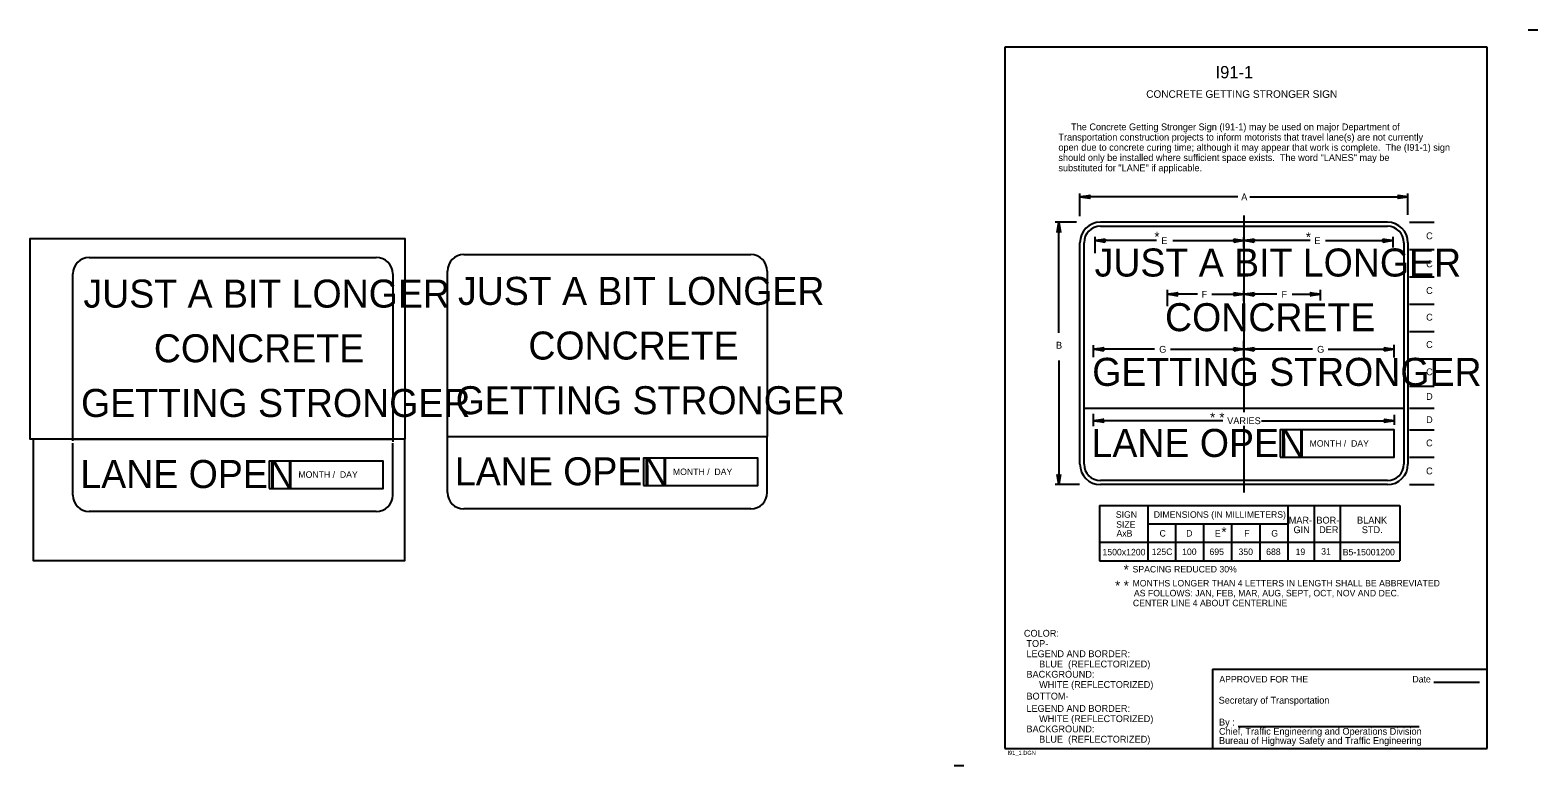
# Model space of a CAD drawing. Extents: x -0.356 to 0.195, y -0.006 to 0.263.
import ezdxf

# ---------------------------------------------------------------- set-up
doc = ezdxf.new("R2010")
doc.units = 0
doc.layers.add('1', color=7, linetype='Continuous')
doc.layers.add('3', color=7, linetype='Continuous')

# ---------------------------------------------------------------- blocks, each defined once
blk = doc.blocks.new('RARROW')
at = {"layer": '3'}
for p, q in [((-2.156, 0.285), (-2.2665, 0.384625)), ((-2.2665, 0.384625), (0, 0)), ((0, 0), (-2.2665, -0.379125)), ((-2.156, 0.285), (-2.075625, 0.12075)), ((0, 0), (-2.156, 0.285)), ((-2.14975, -0.2705), (0, 0)), ((-2.075625, 0.12075), (0, 0)), ((0, 0), (-2.074, -0.108)), ((-2.2665, -0.379125), (-2.14975, -0.2705)), ((-2.074, -0.108), (-2.14975, -0.2705))]:
    blk.add_line(p, q, dxfattribs=at)

msp = doc.modelspace()

# ---------------------------------------------------------------- linework, layer by layer
at = {"layer": '1'}
for p, q in [((0.195, 0.26275), (0.1915, 0.26275)), ((0.1765, 0.2565), (0, 0.2565)), ((0, 0.2565), (0, 0)), ((0.1765, 0), (0.1765, 0.2565)), ((0.076, 0.029), (0.1765, 0.029)), ((0.076, 0.029), (0.076, 0)), ((0.157, 0.02425), (0.173625, 0.02425)), ((0.085375, 0.008), (0.151625, 0.008)), ((0, 0), (0.1765, 0)), ((-0.015, -0.006375), (-0.0185, -0.006375))]:
    msp.add_line(p, q, dxfattribs=at)
at = {"layer": '3'}
for p, q in [((0.0275, 0.19475), (0.0275, 0.203)), ((0.08525, 0.20175), (0.0275, 0.20175)), ((0.089625, 0.20175), (0.1475, 0.20175)), ((0.1475, 0.19525), (0.1475, 0.203)), ((0.0875, 0.195), (0.0875, 0.123)), ((0.02625, 0.1925), (0.0185, 0.1925)), ((0.01975, 0.152), (0.01975, 0.1925)), ((0.14, 0.1925), (0.035, 0.1925)), ((0.035, 0.191), (0.14, 0.191)), ((0.148, 0.1925), (0.157125, 0.1925)), ((0.0275, 0.104), (0.0275, 0.185)), ((0.029, 0.104), (0.029, 0.185)), ((0.033, 0.187125), (0.033, 0.181125)), ((0.0555, 0.18575), (0.033, 0.18575)), ((0.0615, 0.18575), (0.0875, 0.18575)), ((0.0875, 0.18325), (0.0875, 0.187)), ((0.11175, 0.18575), (0.0875, 0.18575)), ((0.117375, 0.18575), (0.142, 0.18575)), ((0.142, 0.187125), (0.142, 0.18325)), ((0.146, 0.185), (0.146, 0.104)), ((0.1475, 0.185), (0.1475, 0.104)), ((0.148, 0.1825), (0.157125, 0.1825)), ((-0.334875, 0.179625), (-0.229875, 0.179625)), ((-0.197875, 0.180625), (-0.092875, 0.180625)), ((-0.340875, 0.1125), (-0.340875, 0.173625)), ((-0.223875, 0.173625), (-0.223875, 0.112125)), ((-0.203875, 0.114125), (-0.203875, 0.174625)), ((-0.086875, 0.174625), (-0.086875, 0.114125)), ((0.148, 0.1725), (0.157125, 0.1725)), ((0.0595, 0.16175), (0.0595, 0.16775)), ((0.0705, 0.166125), (0.0595, 0.166125)), ((0.07575, 0.166125), (0.0875, 0.166125)), ((0.0875, 0.163625), (0.0875, 0.167375)), ((0.0995, 0.166125), (0.0875, 0.166125)), ((0.105125, 0.166125), (0.1155, 0.166125)), ((0.1155, 0.163875), (0.1155, 0.16775)), ((0.148, 0.1625), (0.157125, 0.1625)), ((0.0875, 0.145375), (0.0875, 0.149125)), ((0.148, 0.1525), (0.157125, 0.1525)), ((0.0325, 0.143125), (0.0325, 0.1475)), ((0.05475, 0.146), (0.0325, 0.146)), ((0.060625, 0.146), (0.0875, 0.146)), ((0.0875, 0.1435), (0.0875, 0.14725)), ((0.112625, 0.146), (0.0875, 0.146)), ((0.11825, 0.146), (0.1425, 0.146)), ((0.1425, 0.143), (0.1425, 0.147625)), ((0.01975, 0.141875), (0.01975, 0.0965)), ((0.148, 0.1425), (0.157125, 0.1425)), ((0.148, 0.1325), (0.157125, 0.1325)), ((0.029, 0.1245), (0.146, 0.1245)), ((0.0325, 0.117875), (0.0325, 0.122375)), ((0.1425, 0.122), (0.1425, 0.118375)), ((0.148, 0.1245), (0.157125, 0.1245)), ((0.07975, 0.119875), (0.0325, 0.119875)), ((0.0875, 0.118), (0.0875, 0.093625)), ((0.093875, 0.119875), (0.1425, 0.119875)), ((0.148, 0.1165), (0.157125, 0.1165)), ((-0.340875, 0.113125), (-0.223875, 0.113125)), ((-0.340875, 0.092625), (-0.340875, 0.111625)), ((-0.223875, 0.092625), (-0.223875, 0.111625)), ((-0.203875, 0.114125), (-0.086875, 0.114125)), ((-0.203875, 0.093625), (-0.203875, 0.114125)), ((-0.086875, 0.093625), (-0.086875, 0.114125)), ((0.148, 0.1065), (0.157125, 0.1065)), ((0.027375, 0.0965), (0.0185, 0.0965)), ((0.14, 0.098), (0.035, 0.098)), ((0.14, 0.0965), (0.035, 0.0965)), ((0.148, 0.0965), (0.157125, 0.0965)), ((0.034625, 0.088875), (0.1445, 0.088875)), ((0.034625, 0.088875), (0.034625, 0.068625)), ((0.052375, 0.088875), (0.052375, 0.068625)), ((0.1035, 0.088875), (0.1035, 0.068625)), ((0.113125, 0.088875), (0.113125, 0.068625)), ((0.12275, 0.088875), (0.12275, 0.068625)), ((0.1445, 0.088875), (0.1445, 0.068625)), ((-0.229875, 0.086625), (-0.334875, 0.086625)), ((-0.092875, 0.087625), (-0.197875, 0.087625)), ((0.1035, 0.082), (0.052375, 0.082)), ((0.0625, 0.082), (0.0625, 0.068625)), ((0.07275, 0.082), (0.07275, 0.068625)), ((0.083, 0.082), (0.083, 0.068625)), ((0.09325, 0.082), (0.09325, 0.068625)), ((0.034625, 0.0755), (0.1445, 0.0755)), ((0.034625, 0.068625), (0.1445, 0.068625))]:
    msp.add_line(p, q, dxfattribs=at)
for points in [[(-0.2195, 0.113125), (-0.3565, 0.113125), (-0.3565, 0.1865), (-0.2195, 0.1865)], [(0.10075, 0.1065), (0.1425, 0.1065), (0.1425, 0.1165), (0.10075, 0.1165)], [(-0.2195, 0.113125), (-0.355375, 0.113125), (-0.355375, 0.06875), (-0.2195, 0.06875)], [(-0.269125, 0.095125), (-0.227375, 0.095125), (-0.227375, 0.105125), (-0.269125, 0.105125)], [(-0.132125, 0.096125), (-0.090375, 0.096125), (-0.090375, 0.106125), (-0.132125, 0.106125)]]:
    msp.add_lwpolyline(points, close=True, dxfattribs=at)
for centre, radius, start, end in [((0.035, 0.185), 0.0075, 90, 180), ((0.035, 0.185), 0.006, 90, 180), ((0.14, 0.185), 0.0075, 0, 90), ((0.14, 0.185), 0.006, 0, 90), ((-0.334875, 0.173625), 0.006, 90, 180), ((-0.229875, 0.173625), 0.006, 0, 90), ((-0.197875, 0.174625), 0.006, 90, 180), ((-0.092875, 0.174625), 0.006, 0, 90), ((0.035, 0.104), 0.0075, 180, 270), ((0.035, 0.104), 0.006, 180, 270), ((0.14, 0.104), 0.0075, 270, 0), ((0.14, 0.104), 0.006, 270, 0), ((-0.334875, 0.092625), 0.006, 180, 270), ((-0.229875, 0.092625), 0.006, 270, 0), ((-0.197875, 0.093625), 0.006, 180, 270), ((-0.092875, 0.093625), 0.006, 270, 0)]:
    msp.add_arc(centre, radius, start, end, dxfattribs=at)

# ---------------------------------------------------------------- block references
at = {"layer": '3', "xscale": 0.0016545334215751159, "yscale": 0.0016366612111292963}
for p, rotation in [((0.0275, 0.20175), 180), ((0.01975, 0.1925), 90), ((0.033, 0.18575), 180), ((0.0875, 0.18575), 180), ((0.0595, 0.166125), 180), ((0.0875, 0.166125), 180), ((0.0325, 0.146), 180), ((0.0875, 0.146), 180), ((0.0325, 0.119875), 180), ((0.01975, 0.0965), -90)]:
    msp.add_blockref('RARROW', p, dxfattribs=dict(at, rotation=rotation))
for p in [(0.1475, 0.20175), (0.0875, 0.18575), (0.142, 0.18575), (0.0875, 0.166125), (0.1155, 0.166125), (0.0875, 0.146), (0.1425, 0.146), (0.1425, 0.119875)]:
    msp.add_blockref('RARROW', p, dxfattribs=at)

# ---------------------------------------------------------------- texts
at = {"layer": '1'}
for s, height, p in [('I91-1', 0.0045, (0.077125, 0.245125)), ('CONCRETE GETTING STRONGER SIGN', 0.00275025, (0.05175, 0.238)), ('COLOR:', 0.0024998, (0.007, 0.040875)), (' TOP-', 0.0024998, (0.007, 0.037125)), (' LEGEND AND BORDER:', 0.00249975, (0.007, 0.033375)), (' BACKGROUND:', 0.00249975, (0.007, 0.025875)), ('      BLUE  (REFLECTORIZED)', 0.00249975, (0.007, 0.029625)), ('      WHITE (REFLECTORIZED)', 0.00249975, (0.007, 0.022125)), ('APPROVED FOR THE', 0.00237525, (0.0785, 0.024125)), ('Date ', 0.0023752, (0.149125, 0.024125)), (' BOTTOM-', 0.0024998, (0.007, 0.017875)), ('Secretary of Transportation', 0.00249975, (0.07825, 0.016375)), (' LEGEND AND BORDER:', 0.00249975, (0.007, 0.013375)), ('      WHITE (REFLECTORIZED)', 0.00249975, (0.007, 0.009625)), (' BACKGROUND:', 0.00249975, (0.007, 0.005875)), ('Chief, Traffic Engineering and Operations Division', 0.00249975, (0.078375, 0.005)), ('By :', 0.0024998, (0.078375, 0.008375)), ('      BLUE  (REFLECTORIZED)', 0.00249975, (0.007, 0.002125)), ('Bureau of Highway Safety and Traffic Engineering', 0.00249975, (0.078375, 0.001625)), ('I91_1.DGN', 0.0015, (0.001, -0.002375))]:
    msp.add_text(s, height=height, dxfattribs=at).set_placement(p)
at = {"layer": '3'}
for s, height, p in [('     The Concrete Getting Stronger Sign (I91-1) may be used on major Department of', 0.00249975, (0.019625, 0.226125)), ('Transportation construction projects to inform motorists that travel lane(s) are not currently', 0.00249975, (0.019625, 0.222375)), ('open due to concrete curing time; although it may appear that work is complete.  The (I91-1) sign ', 0.00249975, (0.019625, 0.218625)), ('should only be installed where sufficient space exists.  The word "LANES" may be', 0.00249975, (0.019625, 0.214875)), ('substituted for "LANE" if applicable.', 0.00249975, (0.019625, 0.211125)), ('A', 0.0025, (0.0865, 0.2005)), ('*', 0.003599, (0.05475, 0.185375)), ('*', 0.003599, (0.110125, 0.18525)), ('C', 0.0025, (0.154125, 0.18625)), ('JUST A BIT LONGER', 0.01025025, (0.032875, 0.172625)), ('E', 0.0025, (0.05725, 0.1845)), ('E', 0.0025, (0.11325, 0.1845)), ('C', 0.0025, (0.154125, 0.176)), ('JUST A BIT LONGER', 0.01025025, (-0.337, 0.16125)), ('JUST A BIT LONGER', 0.01025025, (-0.2, 0.16225)), ('F', 0.0025, (0.072, 0.164875)), ('F', 0.0025, (0.10125, 0.164875)), ('C', 0.0025, (0.154125, 0.16625)), ('CONCRETE', 0.0102502, (0.058625, 0.152625)), ('C', 0.0025, (0.154125, 0.1565)), ('CONCRETE', 0.0102502, (-0.31125, 0.14125)), ('CONCRETE', 0.0102502, (-0.17425, 0.14225)), ('C', 0.0025, (0.154125, 0.1465)), ('B', 0.0025, (0.01875, 0.14625)), ('G', 0.0025, (0.0565, 0.14475)), ('G', 0.0025, (0.11425, 0.14475)), ('GETTING STRONGER', 0.01025025, (0.032, 0.132625)), ('C', 0.0025, (0.154125, 0.1365)), ('GETTING STRONGER', 0.01025025, (-0.200875, 0.12225)), ('GETTING STRONGER', 0.01025025, (-0.337875, 0.12125)), ('D', 0.0025, (0.154125, 0.1275)), ('*', 0.003599, (0.075125, 0.11925)), ('*', 0.003599, (0.0785, 0.11925)), ('D', 0.0025, (0.154125, 0.119)), ('LANE OPEN', 0.0102502, (0.03175, 0.106625)), ('VARIES', 0.0024998, (0.081375, 0.118625)), ('MONTH /  DAY', 0.00237525, (0.1115, 0.110375)), ('C', 0.0025, (0.154125, 0.1105)), ('LANE OPEN', 0.0102502, (-0.338125, 0.09525)), ('LANE OPEN', 0.0102502, (-0.201125, 0.09625)), ('MONTH /  DAY', 0.00237525, (-0.258375, 0.099)), ('MONTH /  DAY', 0.00237525, (-0.121375, 0.1)), ('C', 0.0025, (0.154125, 0.10025)), ('SIGN', 0.0023752, (0.040625, 0.084375)), ('SIZE', 0.0023752, (0.04075, 0.08075)), ('DIMENSIONS (IN MILLIMETERS)', 0.00237525, (0.0545, 0.084375)), ('MAR-', 0.0024998, (0.103875, 0.08225)), ('BOR-', 0.0024998, (0.114, 0.08225)), ('BLANK', 0.0024998, (0.128875, 0.08225)), ('AxB', 0.0023752, (0.040875, 0.0775)), ('C', 0.002375, (0.056625, 0.0775)), ('D', 0.002375, (0.066375, 0.0775)), ('E', 0.002375, (0.076875, 0.0775)), ('*', 0.003599, (0.07925, 0.077375)), ('F', 0.002375, (0.087625, 0.0775)), ('G', 0.002375, (0.0975, 0.0775)), ('GIN', 0.0024998, (0.105625, 0.07875)), ('DER', 0.0024998, (0.115, 0.07875)), ('STD.', 0.0024998, (0.130625, 0.07875)), ('1500x1200', 0.0023752, (0.03575, 0.070625)), ('125C', 0.0023752, (0.05375, 0.07075)), ('100', 0.0023752, (0.064875, 0.07075)), ('695', 0.0023752, (0.074875, 0.07075)), ('350', 0.0023752, (0.0855, 0.07075)), ('688', 0.0023752, (0.095625, 0.07075)), ('19', 0.0023752, (0.106375, 0.07075)), ('31', 0.0023752, (0.11575, 0.070875)), ('B5-15001200', 0.00237525, (0.123625, 0.070625)), ('*', 0.003599, (0.0435, 0.063625)), ('SPACING REDUCED 30%', 0.00237525, (0.04675, 0.064375)), ('*', 0.003599, (0.040375, 0.05775)), ('*', 0.003599, (0.0435, 0.05775)), ('MONTHS LONGER THAN 4 LETTERS IN LENGTH SHALL BE ABBREVIATED', 0.00237525, (0.04675, 0.05925)), ('AS FOLLOWS: JAN, FEB, MAR, AUG, SEPT, OCT, NOV AND DEC.', 0.00237525, (0.04725, 0.055625)), ('CENTER LINE 4 ABOUT CENTERLINE', 0.00237525, (0.046875, 0.052))]:
    msp.add_text(s, height=height, dxfattribs=at).set_placement(p)

doc.saveas('drawing.dxf')
